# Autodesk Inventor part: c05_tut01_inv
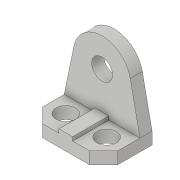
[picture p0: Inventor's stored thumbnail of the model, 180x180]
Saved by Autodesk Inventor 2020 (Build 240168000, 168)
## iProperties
Created: 2017-04
Part Number: c05_tut01_inv
Material: Generic
Document SubType Name: Modeling
Designer: CADCIM 00
Density: 1 g/cm^3
Appearance: Default
Author: CADCIM 00
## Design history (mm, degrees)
sketch "Sketch1"
  geometry: L1 (0, 0)-(-200, 0); L2 (-200, 0)-(-200, -90); L3 (-200, -90)-(-162, -128); L4 (-162, -128)-(-38, -128); L5 (-38, -128)-(0, -90); L6 (0, -90)-(0, 0); L7 (-200, -90)-(0, -90); C1 r 26 at (-154, -74); C2 r 26 at (-46, -74)
  constraints: 14 end point, 3 horizontal, 3 perpendicular, 2 centre point, 1 equal radius, 1 horizontal alignment
  dimensions: "d0" = 90 distance of L1.end L2.end; "d1" = 128 distance between parallel lines of L1 L4; "d2" = 38 distance from line of L3.end L2; "d3" = 124 distance of L3.end L4.end; "d4" = 46 distance from line of L2 C1.centre; "d5" = 74 distance from line of L1 C1.centre; "d6" = 52 diameter of C1; "d7" = 46 distance from line of L6 C2.centre
extrude "Extrusion1" new body sketch "Sketch1" distance "d8" = 32; taper "d9" = 0 deg
sketch "Sketch2"
  geometry: L1 (200, -32)-(0, -32) reference; L2 (200, -32)-(174.418, -155.424); L3 (25.582, -155.424)-(0, -32); L4 (0, -32)-(200, -32); L5 (100, -32)-(100, -140); C1 r 27.5 at (100, -140); A1 r 76 centre (100, -140) between (25.582, -155.424) and (174.418, -155.424); 1 further point
  constraints: 8 end point, 2 centre point, 2 point on circle, 2 tangent, 1 coincident, 1 collinear, 1 midpoint, 1 vertical
  dimensions: "d10" = 55 diameter of C1; "d11" = 76 radius of A1; "d12" = 108 distance from line of L1 A1.centre
extrude "Extrusion2" join sketch "Sketch2" distance "d13" = 32; taper "d14" = 0 deg
sketch "Sketch3"
  geometry: L1 (82, 42)-(118, 42); L2 (118, 42)-(118, 32); L3 (118, 32)-(82, 32); L4 (82, 32)-(82, 42); L5 (38, 32)-(162, 32) reference; L6 (0, 0)-(0, 32) reference; 1 further point
  constraints: 8 end point, 2 parallel, 1 collinear, 1 horizontal, 1 perpendicular
  dimensions: "d15" = 10 distance between parallel lines of L3 L1; "d16" = 36 distance of L1.start L1.end; "d17" = 82 distance from line of L6 L1.start
extrude "Extrusion3" join sketch "Sketch3" stored distance "d18" = 32; taper "d19" = 0 deg
body "Solid1"
